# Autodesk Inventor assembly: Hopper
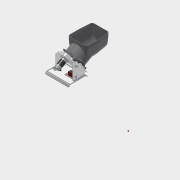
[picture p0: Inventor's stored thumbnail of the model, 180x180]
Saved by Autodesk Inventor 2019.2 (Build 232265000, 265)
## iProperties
Created: 2005-11
Part Number: Hopper
Document SubType Name: Assembly
Designer: floress
Mass: 1174.02 g
Surface Area: 4875.06 cm^2
Volume: 968.711 cm^3
Density: 1.21194 g/cm^3
Author: floress
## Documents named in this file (16)
- D:\Slotmachine\Workspaces\Workspace\Cabinet\Hopper\Hopper.iam
- D:\Slotmachine\Workspaces\Workspace\Cabinet\Hopper\Hopper - Base Plate.ipt
- D:\Slotmachine\Workspaces\Workspace\Cabinet\Hopper\Hopper - Frame Left.ipt
- D:\Slotmachine\Workspaces\Workspace\Cabinet\Hopper\Hopper - Frame Right.ipt
- D:\Slotmachine\Workspaces\Workspace\Cabinet\Hopper\Hopper - Housing Unit.ipt
- D:\Slotmachine\Workspaces\Workspace\Cabinet\Hopper\Hopper - Motor.ipt
- D:\Slotmachine\Workspaces\Workspace\Cabinet\Hopper\Hopper - Gear Box.ipt
- D:\Slotmachine\Workspaces\Workspace\Cabinet\Hopper\Hopper - Coin Plate.ipt
- D:\Slotmachine\Workspaces\Workspace\Cabinet\Hopper\Hopper - Knife.ipt
- D:\Slotmachine\Workspaces\Workspace\Cabinet\Hopper\Hopper - Coin Guide.ipt
- D:\Slotmachine\Workspaces\Workspace\Cabinet\Hopper\Hopper - Coin Plate Guard.ipt
- D:\Slotmachine\Workspaces\Workspace\Cabinet\Hopper\Hopper - Bucket.ipt
- D:\Slotmachine\Workspaces\Workspace\Cabinet\Hopper\Hopper - Handle.ipt
- D:\Slotmachine\Workspaces\Workspace\Cabinet\Hopper\Hopper - Relay.ipt
- D:\Slotmachine\Workspaces\Workspace\Cabinet\Hopper\Hopper - Switch.ipt
- D:\Slotmachine\Workspaces\Workspace\Cabinet\Hopper\Hopper - Switch Lever.iam
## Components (16 placed, 15 different names)
1. Hopper - Base Plate:1 — Mate:1, Mate:2, Mate:5, Mate:6, Mate:11, Mate:12, Mate:38
2. Hopper - Frame Left:1 — Mate:1, Mate:7, Mate:8, Mate:11, Mate:12, Mate:35, Mate:36, Mate:37
3. Hopper - Frame Right:1 — Mate:2, Mate:5, Mate:6, Mate:9, Mate:10, Insert:1, Angle:1
4. Hopper - Housing Unit:1 — Mate:7, Mate:8, Mate:9, Mate:10, Mate:14, Mate:15, Mate:16, Mate:17, Mate:23, Mate:24, Mate:25, Mate:26, Mate:27, Mate:28, Mate:29, Mate:30, Mate:31, Mate:32, Mate:33, Mate:34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
5. Hopper - Gear Box:1 — Mate:14, Mate:15, Mate:16, Mate:17, Mate:13, Mate:18, Mate:19, Mate:20, Mate:21, Mate:22
6. Hopper - Motor:1 — Mate:13, Mate:18, Mate:19
7. Hopper - Coin Plate:1 — Mate:20, Mate:21, Mate:22
8. Hopper - Knife:1 — Mate:23, Mate:24, Mate:25
9. Hopper - Coin Guide:1 — Mate:26, Mate:27, Mate:28
10. Hopper - Coin Plate Guard:1 — Mate:29, Mate:30, Mate:31
11. Hopper - Bucket:1 — Mate:32, Mate:33, Mate:34
12. Hopper - Handle:1 — Mate:35, Mate:36, Mate:37
13. Hopper - Relay:1 — Mate:38
14. Hopper - Switch Lever:1 [sub-assembly] — Mate:62, Mate:63, Mate:64
15. Hopper - Switch:1 — Mate:43
16. Hopper - Handle:2 — Insert:1, Angle:1
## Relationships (42: Mate 40, Insert 1, Angle 1)
- Mate:1: Hopper - Base Plate:1 ↔ Hopper - Frame Left:1
- Mate:2: Hopper - Base Plate:1 ↔ Hopper - Frame Right:1
- Mate:5: Hopper - Base Plate:1 ↔ Hopper - Frame Right:1
- Mate:6: Hopper - Base Plate:1 ↔ Hopper - Frame Right:1
- Mate:7: Hopper - Frame Left:1 ↔ Hopper - Housing Unit:1
- Mate:8: Hopper - Frame Left:1 ↔ Hopper - Housing Unit:1
- Mate:9: Hopper - Frame Right:1 ↔ Hopper - Housing Unit:1
- Mate:10: Hopper - Frame Right:1 ↔ Hopper - Housing Unit:1
- Mate:11: Hopper - Base Plate:1 ↔ Hopper - Frame Left:1
- Mate:12: Hopper - Base Plate:1 ↔ Hopper - Frame Left:1
- Mate:14: Hopper - Housing Unit:1 ↔ Hopper - Gear Box:1
- Mate:15: Hopper - Housing Unit:1 ↔ Hopper - Gear Box:1
- Mate:16: Hopper - Housing Unit:1 ↔ Hopper - Gear Box:1
- Mate:17: Hopper - Housing Unit:1 ↔ Hopper - Gear Box:1
- Mate:13: Hopper - Gear Box:1 ↔ Hopper - Motor:1
- Mate:18: Hopper - Gear Box:1 ↔ Hopper - Motor:1
- Mate:19: Hopper - Gear Box:1 ↔ Hopper - Motor:1
- Mate:20: Hopper - Gear Box:1 ↔ Hopper - Coin Plate:1
- Mate:21: Hopper - Gear Box:1 ↔ Hopper - Coin Plate:1
- Mate:22: Hopper - Gear Box:1 ↔ Hopper - Coin Plate:1
- Mate:23: Hopper - Housing Unit:1 ↔ Hopper - Knife:1
- Mate:24: Hopper - Housing Unit:1 ↔ Hopper - Knife:1
- Mate:25: Hopper - Housing Unit:1 ↔ Hopper - Knife:1
- Mate:26: Hopper - Housing Unit:1 ↔ Hopper - Coin Guide:1
- Mate:27: Hopper - Housing Unit:1 ↔ Hopper - Coin Guide:1
- Mate:28: Hopper - Housing Unit:1 ↔ Hopper - Coin Guide:1
- Mate:29: Hopper - Housing Unit:1 ↔ Hopper - Coin Plate Guard:1
- Mate:30: Hopper - Housing Unit:1 ↔ Hopper - Coin Plate Guard:1
- Mate:31: Hopper - Housing Unit:1 ↔ Hopper - Coin Plate Guard:1
- Mate:32: Hopper - Housing Unit:1 ↔ Hopper - Bucket:1
- Mate:33: Hopper - Housing Unit:1 ↔ Hopper - Bucket:1
- Mate:34: Hopper - Housing Unit:1 ↔ Hopper - Bucket:1
- Mate:35: Hopper - Frame Left:1 ↔ Hopper - Handle:1
- Mate:36: Hopper - Frame Left:1 ↔ Hopper - Handle:1
- Mate:37: Hopper - Frame Left:1 ↔ Hopper - Handle:1
- Mate:38: Hopper - Base Plate:1 ↔ Hopper - Relay:1
- Mate:43: Hopper - Housing Unit:1 ↔ Hopper - Switch:1
- Mate:62: Hopper - Housing Unit:1 ↔ Hopper - Switch Lever:1
- Mate:63: Hopper - Housing Unit:1 ↔ Hopper - Switch Lever:1
- Mate:64: Hopper - Housing Unit:1 ↔ Hopper - Switch Lever:1
- Insert:1: Hopper - Frame Right:1 ↔ Hopper - Handle:2
- Angle:1: Hopper - Frame Right:1 ↔ Hopper - Handle:2
